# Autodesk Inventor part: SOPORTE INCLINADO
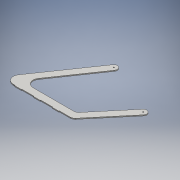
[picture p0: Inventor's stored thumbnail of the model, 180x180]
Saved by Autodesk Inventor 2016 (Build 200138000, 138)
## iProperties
Created: 2016-06
Part Number: SOPORTE INCLINADO
Material: Genérico
Document SubType Name: Modeling
Designer: adm
Density: 1 g/cm^3
Appearance: Valor por defecto
Author: adm
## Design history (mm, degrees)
sketch "Boceto1"
  geometry: L1 (75.83, -250.697)-(257.434, -34.269); L2 (57.178, -210.697)-(226.793, -8.558); L3 (34.196, -221.414)-(-203.95, -221.414); L4 (-54.297, 107.267)-(-236.927, -158.776); L5 (-87.275, 129.905)-(-312.904, -198.776); L6 (-269.73, -261.414)-(-269.73, -264.414); L7 (-229.73, -261.414)-(-229.73, -264.414); L8 (-159.73, -261.414)-(-159.73, -264.414); L9 (-119.73, -261.414)-(-119.73, -264.414); L10 (-49.73, -261.414)-(-49.73, -264.414); L11 (-9.73, -261.414)-(-9.73, -264.414); L12 (-49.73, -264.414)-(-9.73, -264.414); L13 (-269.73, -264.414)-(-229.73, -264.414); L14 (-159.73, -264.414)-(-119.73, -264.414); L15 (52.849, -261.414)-(-9.73, -261.414); L16 (-49.73, -261.414)-(-119.73, -261.414); L17 (-159.73, -261.414)-(-229.73, -261.414); L18 (-269.73, -261.414)-(-279.926, -261.414); C1 r 3.25 at (242.114, -21.414); C2 r 3.25 at (-70.786, 118.586); A1 r 30 centre (52.849, -231.414) between (52.849, -261.414) and (75.83, -250.697); A2 r 20 centre (242.114, -21.414) between (257.434, -34.269) and (226.793, -8.558); A3 r 30 centre (34.196, -191.414) between (34.196, -221.414) and (57.178, -210.697); A4 r 20 centre (-70.786, 118.586) between (-54.297, 107.267) and (-87.275, 129.905); A5 r 40 centre (-203.95, -181.414) between (-236.927, -158.776) and (-203.95, -221.414); A6 r 40 centre (-279.926, -221.414) between (-312.904, -198.776) and (-279.926, -261.414); 3 further points
  constraints: 36 end point, 15 tangent, 13 point on circle, 8 centre point, 3 coincident, 3 horizontal, 3 horizontal alignment, 1 point on line
  dimensions: "d3" = 40 radius of A6; "d5" = 40 radius of A5; "d6" = 30 radius of A3; "d7" = 30 radius of A1; "d20" = 6.5 diameter of C2; "d21" = 6.5 diameter of C1; "d38" = 240 distance from line of C1.centre L15; "d39" = 40 distance between parallel lines of L16 L3; "d40" = 40 distance between parallel lines of L2 L1; "d41" = 40 distance between parallel lines of L5 L4; "d42" = 62.57873 distance of L15.start L11.start; "d43" = 3 distance of L10.start L10.end; "d44" = 3 distance of L11.start L11.end; "d45" = 238.14615 distance of L3.start L3.end; "d46" = 20 radius of A2; "d47" = 380 distance from line of C2.centre L16; "d48" = 20 radius of A4; "d49" = 130 deg angle of L3 L2
extrude "Extrusión1" new body sketch "Boceto1" distance "d18" = 6; taper "d19" = 0 deg
node "Sólido1"
other parameters: "d4" = 50 deg, "d11" = 3, "d23" = 3, "d33" = 3, "d34" = 2
